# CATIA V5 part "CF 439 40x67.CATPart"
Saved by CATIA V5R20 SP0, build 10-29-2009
Part number: CF 439 40x67
Definition: NONE
Nomenclature: CF 439 40x67
Source: Unknown
Description: CF 439 40x67
Bounding box of the stored display mesh (mm): x -31.5 to 31.5, y 0 to 67, z -31.5 to 31.5
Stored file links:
  C:\Users\Utente\Desktop\IO LAVORO\3D X SITO CF\X SITO\CF 439\CF 439 40x67.CATPart
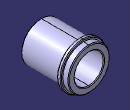
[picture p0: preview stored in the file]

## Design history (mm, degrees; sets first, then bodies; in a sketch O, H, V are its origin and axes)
Body1 "CF 439 40x67" (main body)
  Solid1: solid without history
